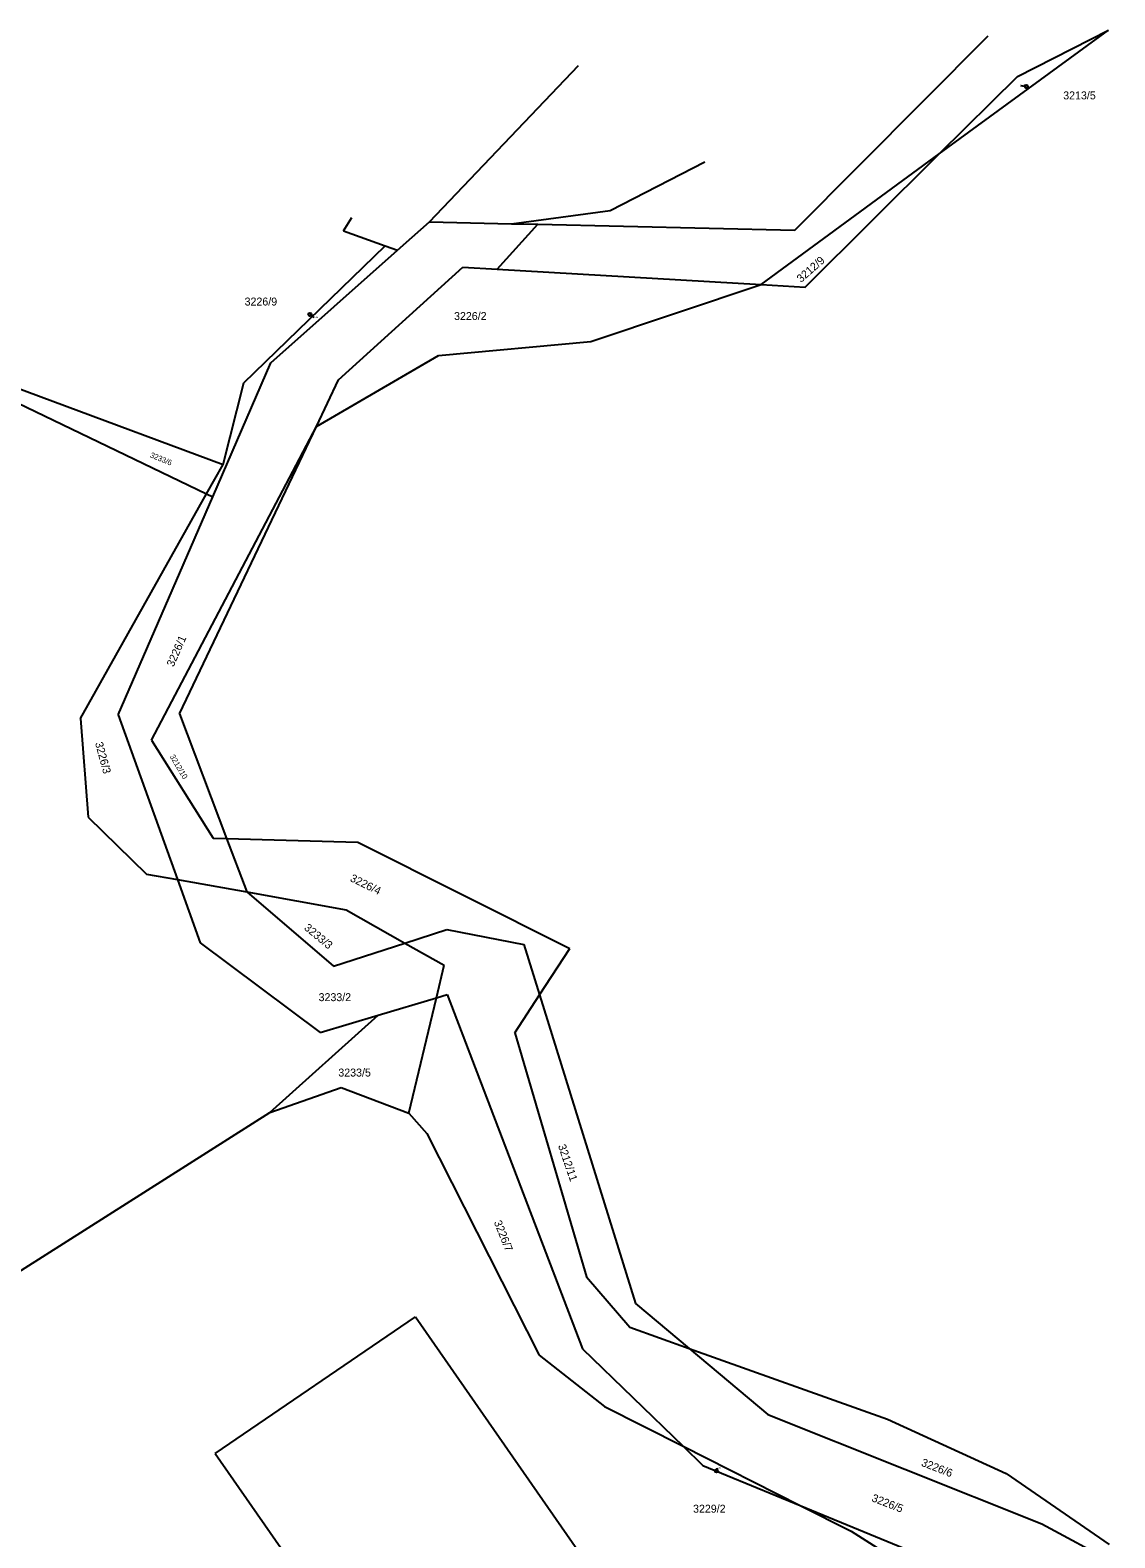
# Model space of a CAD drawing. Extents: x -722132 to -721608, y -1046877 to -1046449.
# Drawn here: x -721811.3 to -721695.4, y -1046609.9 to -1046448.7 of the extents above; entities that cross this region are included whole.
import ezdxf

# ---------------------------------------------------------------- set-up
doc = ezdxf.new("R2010")
doc.units = 0
for name, color, linetype in [('Vrstva 1', 7, 'Continuous'), ('Vrstva 16', 7, 'Continuous'), ('Vrstva 18', 7, 'Continuous'), ('Vrstva 4', 7, 'Continuous'), ('Vrstva 6', 7, 'Continuous')]:
    doc.layers.add(name, color=color, linetype=linetype)

msp = doc.modelspace()

# ---------------------------------------------------------------- linework, layer by layer
at = {"layer": 'Vrstva 1'}
for points in [[(-721714.15, -1046461.91), (-721696.06, -1046448.67)], [(-721768.66, -1046469.17), (-721752.73, -1046452.44)], [(-721749.34, -1046467.95), (-721739.22, -1046462.74)], [(-721733.2, -1046475.86), (-721714.15, -1046461.91)], [(-721728.47, -1046476.14), (-721714.15, -1046461.91)], [(-721759.87, -1046469.37), (-721749.34, -1046467.95)], [(-721777.84, -1046470.12), (-721776.94, -1046468.69)], [(-721770.49, -1046470.8), (-721768.66, -1046469.17)], [(-721768.66, -1046469.17), (-721759.87, -1046469.37)], [(-721777.84, -1046470.12), (-721773.37, -1046471.72)], [(-721788.49, -1046486.39), (-721773.37, -1046471.72)], [(-721751.4, -1046481.95), (-721733.2, -1046475.86)], [(-721733.2, -1046475.86), (-721728.47, -1046476.14)], [(-721767.69, -1046483.47), (-721751.4, -1046481.95)], [(-721780.74, -1046491.03), (-721767.69, -1046483.47)], [(-721790.7, -1046495.09), (-721788.49, -1046486.39)], [(-721798.38, -1046524.57), (-721780.74, -1046491.03)], [(-721795.37, -1046521.76), (-721780.74, -1046491.03)], [(-721792.48, -1046498.26), (-721790.7, -1046495.09)], [(-721805.96, -1046522.28), (-721792.48, -1046498.26)], [(-721805.96, -1046522.28), (-721805.14, -1046532.82)], [(-721795.37, -1046521.76), (-721790.34, -1046535.08)], [(-721798.38, -1046524.57), (-721791.78, -1046535.04)], [(-721805.14, -1046532.82), (-721798.88, -1046538.89)], [(-721791.78, -1046535.04), (-721790.34, -1046535.08)], [(-721790.34, -1046535.08), (-721776.31, -1046535.5)], [(-721790.34, -1046535.08), (-721788.18, -1046540.81)], [(-721776.31, -1046535.5), (-721753.66, -1046546.84)], [(-721798.88, -1046538.89), (-721795.59, -1046539.48)], [(-721795.59, -1046539.48), (-721793.16, -1046546.25)], [(-721795.59, -1046539.48), (-721788.18, -1046540.81)], [(-721788.18, -1046540.81), (-721777.54, -1046542.72)], [(-721788.18, -1046540.81), (-721778.89, -1046548.73)], [(-721777.54, -1046542.72), (-721771.27, -1046546.27)], [(-721793.16, -1046546.25), (-721780.35, -1046555.85)], [(-721778.89, -1046548.73), (-721771.27, -1046546.27)], [(-721771.27, -1046546.27), (-721767.07, -1046548.64)], [(-721756.88, -1046551.81), (-721753.66, -1046546.84)], [(-721767.91, -1046552.13), (-721767.07, -1046548.64)], [(-721759.52, -1046555.88), (-721756.88, -1046551.81)], [(-721756.88, -1046551.81), (-721746.64, -1046584.8)], [(-721774.12, -1046553.99), (-721767.91, -1046552.13)], [(-721770.86, -1046564.47), (-721767.91, -1046552.13)], [(-721780.35, -1046555.85), (-721774.12, -1046553.99)], [(-721759.52, -1046555.88), (-721751.85, -1046581.95)], [(-721785.73, -1046564.38), (-721778.09, -1046561.72)], [(-721778.09, -1046561.72), (-721770.86, -1046564.47)], [(-721816.4, -1046583.83), (-721785.73, -1046564.38)], [(-721770.86, -1046564.47), (-721768.94, -1046566.62)], [(-721768.94, -1046566.62), (-721756.91, -1046590.32)], [(-721751.85, -1046581.95), (-721747.24, -1046587.35)], [(-721746.64, -1046584.8), (-721740.88, -1046589.62)], [(-721747.24, -1046587.35), (-721740.88, -1046589.62)], [(-721756.91, -1046590.32), (-721749.93, -1046595.83)], [(-721740.88, -1046589.62), (-721719.7, -1046597.18)], [(-721749.93, -1046595.83), (-721741.54, -1046600.07)], [(-721719.7, -1046597.18), (-721707.01, -1046602.99)], [(-721741.54, -1046600.07), (-721729.02, -1046606.4)], [(-721741.54, -1046600.07), (-721739.44, -1046602.11)], [(-721739.44, -1046602.11), (-721729.02, -1046606.4)], [(-721707.01, -1046602.99), (-721695.99, -1046610.56)], [(-721729.02, -1046606.4), (-721723.56, -1046609.16)], [(-721723.56, -1046609.16), (-721716.21, -1046613.8)]]:
    msp.add_lwpolyline(points, dxfattribs=at)
at = {"layer": 'Vrstva 16'}
for points in [[(-721705.46, -1046454.58), (-721704.85, -1046454.69)], [(-721780.98, -1046479.4), (-721781.43, -1046479.06)], [(-721737.93, -1046602.42), (-721737.97, -1046602.71)]]:
    msp.add_lwpolyline(points, dxfattribs=at)
for centre in [(-721704.85, -1046454.69), (-721781.43, -1046479.06), (-721737.97, -1046602.71)]:
    msp.add_circle(centre, 0.175, dxfattribs=at)
at = {"layer": 'Vrstva 4'}
for points in [[(-721791.55, -1046600.86), (-721770.14, -1046586.22)], [(-721770.14, -1046586.22), (-721726.8, -1046648.56)], [(-721791.55, -1046600.86), (-721748.12, -1046663.26)]]:
    msp.add_lwpolyline(points, dxfattribs=at)
at = {"layer": 'Vrstva 6'}
for points in [[(-721705.8, -1046453.62), (-721696.06, -1046448.67)], [(-721729.58, -1046470.05), (-721708.92, -1046449.26)], [(-721714.15, -1046461.91), (-721705.8, -1046453.62)], [(-721761.4, -1046474.21), (-721757.08, -1046469.43)], [(-721759.87, -1046469.37), (-721757.08, -1046469.43)], [(-721757.08, -1046469.43), (-721729.58, -1046470.05)], [(-721772.05, -1046472.19), (-721770.49, -1046470.8)], [(-721785.6, -1046484.25), (-721772.05, -1046472.19)], [(-721773.37, -1046471.72), (-721772.05, -1046472.19)], [(-721778.37, -1046486.06), (-721765.09, -1046474)], [(-721765.09, -1046474), (-721761.4, -1046474.21)], [(-721761.4, -1046474.21), (-721733.2, -1046475.86)], [(-721827.15, -1046481.57), (-721790.7, -1046495.09)], [(-721827.15, -1046481.57), (-721792.48, -1046498.26)], [(-721791.81, -1046498.58), (-721785.6, -1046484.25)], [(-721780.74, -1046491.03), (-721778.37, -1046486.06)], [(-721801.91, -1046521.87), (-721791.81, -1046498.58)], [(-721792.48, -1046498.26), (-721791.81, -1046498.58)], [(-721801.91, -1046521.87), (-721795.59, -1046539.48)], [(-721771.27, -1046546.27), (-721766.79, -1046544.82)], [(-721766.79, -1046544.82), (-721758.55, -1046546.42)], [(-721758.55, -1046546.42), (-721756.88, -1046551.81)], [(-721767.91, -1046552.13), (-721766.74, -1046551.78)], [(-721766.74, -1046551.78), (-721752.28, -1046589.65)], [(-721785.73, -1046564.38), (-721774.12, -1046553.99)], [(-721752.28, -1046589.65), (-721741.54, -1046600.07)], [(-721740.88, -1046589.62), (-721732.46, -1046596.67)], [(-721732.46, -1046596.67), (-721703.18, -1046608.36)], [(-721729.02, -1046606.4), (-721704.27, -1046616.59)], [(-721703.18, -1046608.36), (-721695.38, -1046612.55)]]:
    msp.add_lwpolyline(points, dxfattribs=at)

# ---------------------------------------------------------------- texts
at = {"layer": 'Vrstva 16'}
for s, p in [('3213/5', (-721700.9, -1046456.07)), ('3226/9', (-721788.41, -1046478.11)), ('3229/2', (-721740.47, -1046607.17))]:
    msp.add_text(s, height=0.85, dxfattribs=at).set_placement(p)
at = {"layer": 'Vrstva 18'}
for s, height, p in [('3213/5', 0.1, (-721705.46, -1046454.58)), ('3226/9', 0.1, (-721780.98, -1046479.4)), ('3226/2', 0.85, (-721766.02, -1046479.66)), ('3233/2', 0.85, (-721780.5, -1046552.48)), ('3233/5', 0.85, (-721778.39, -1046560.54)), ('3229/2', 0.1, (-721737.93, -1046602.42))]:
    msp.add_text(s, height=height, dxfattribs=at).set_placement(p)
for s, height, rotation, p in [('3212/9', 0.85, 41.1709, (-721728.93, -1046475.7)), ('3233/6', 0.595, 337.8057, (-721798.57, -1046494.32)), ('3226/1', 0.85, 66.3248, (-721796.01, -1046516.81)), ('3226/3', 0.85, 285.3004, (-721804.41, -1046524.89)), ('3212/10', 0.595, 300.5386, (-721796.43, -1046526.33)), ('3226/4', 0.85, 333.7302, (-721777.21, -1046539.61)), ('3233/3', 0.85, 320.3341, (-721782.12, -1046544.76)), ('3212/11', 0.85, 288.8673, (-721754.92, -1046567.94)), ('3226/7', 0.85, 291.7838, (-721761.78, -1046576.11)), ('3226/6', 0.85, 338.7082, (-721716.16, -1046602.13)), ('3226/5', 0.85, 338.7082, (-721721.45, -1046605.92))]:
    msp.add_text(s, height=height, rotation=rotation, dxfattribs=at).set_placement(p)

doc.saveas('drawing.dxf')
